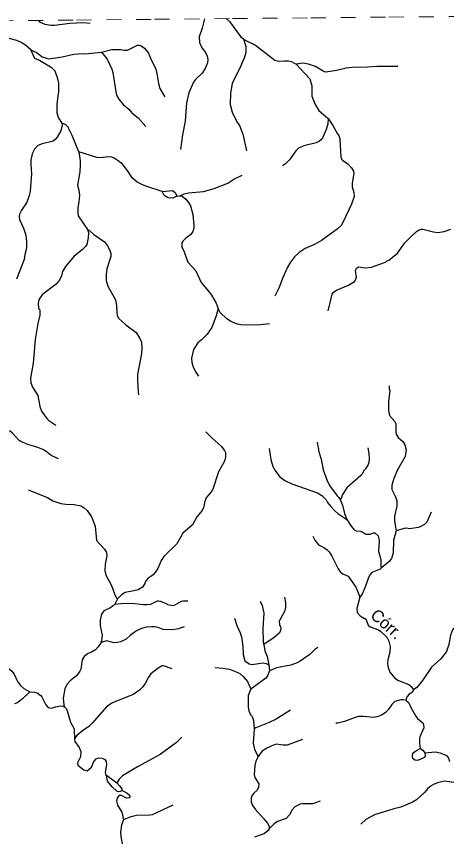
# Model space of a CAD drawing. Extents: x 346.5 to 372.4, y 7400.3 to 7428.2.
# Drawn here: x 359.2 to 362.07, y 7422.68 to 7428.16 of the extents above; entities that cross this region are included whole.
import ezdxf
from ezdxf.enums import TextEntityAlignment as Align

# ---------------------------------------------------------------- set-up
doc = ezdxf.new("R2010")
doc.units = 0
doc.header["$LTSCALE"] = 0.032
doc.linetypes.add('SHORT_DASHED', pattern=[2.7, 1.5, -1.2])
for name, color, linetype, lineweight in [('2', 7, 'Continuous', 25), ('53', 7, 'SHORT_DASHED', 13), ('7', 7, 'Continuous', 25)]:
    doc.layers.add(name, color=color, linetype=linetype, lineweight=lineweight)
doc.layers.add('61', color=7, linetype='Continuous')

msp = doc.modelspace()

# ---------------------------------------------------------------- linework, layer by layer
at = {"layer": '2'}
for points in [[(360.1729, 7426.9861), (360.242, 7426.9932), (360.2587, 7426.9788), (360.2709, 7426.9555), (360.2438, 7426.9425), (360.2123, 7426.9445), (360.1856, 7426.9603)], [(361.8965, 7423.2635), (361.9141, 7423.2527), (361.9279, 7423.2355), (361.9302, 7423.2133), (361.9226, 7423.2035), (361.8958, 7423.1911), (361.876, 7423.1845), (361.8606, 7423.1871), (361.8483, 7423.1979), (361.8447, 7423.2143), (361.8488, 7423.2333), (361.8606, 7423.2451)], [(359.7998, 7423.0853), (359.869, 7423.0347), (359.8883, 7423.0151), (359.9024, 7422.9939), (359.9058, 7422.9835), (359.8927, 7422.978), (359.8796, 7422.9754), (359.87, 7422.9793), (359.839, 7423.0083), (359.8067, 7423.0468)]]:
    msp.add_lwpolyline(points, close=True, dxfattribs=at)
at = {"layer": '53'}
msp.add_lwpolyline([(355.9458, 7428.0971), (356.4678, 7428.1021), (356.9898, 7428.1072), (357.5118, 7428.1122), (358.0338, 7428.1172), (358.5558, 7428.1222), (359.0778, 7428.1271), (359.5998, 7428.1321), (360.1218, 7428.137), (360.6438, 7428.1419), (361.1658, 7428.1468), (361.6878, 7428.1517), (362.2098, 7428.1565)], dxfattribs=at)
at = {"layer": '7'}
msp.add_line((360.2709, 7426.9555), (360.2939, 7426.9584), dxfattribs=at)
for points in [[(359.6922, 7428.1092), (359.6452, 7428.114), (359.5559, 7428.11), (359.4539, 7428.0949), (359.4284, 7428.0949), (359.3902, 7428.102), (359.36, 7428.1166), (359.3492, 7428.1297)], [(360.4549, 7428.1401), (360.4405, 7428.0773), (360.4206, 7428.02), (360.4214, 7427.9825), (360.4373, 7427.9466), (360.4612, 7427.9164), (360.474, 7427.8909), (360.4772, 7427.8685), (360.4756, 7427.8462), (360.4596, 7427.808), (360.4397, 7427.7769), (360.3959, 7427.7346), (360.3831, 7427.7179), (360.3513, 7427.6454), (360.3361, 7427.5785), (360.3258, 7427.4557), (360.3082, 7427.3649), (360.2955, 7427.2669)], [(360.5994, 7428.1415), (360.6222, 7428.122), (360.6967, 7428.0219), (360.7173, 7428.0074)], [(359.2939, 7427.9329), (359.2595, 7427.965), (359.2308, 7427.9825), (359.2021, 7427.9952), (359.1415, 7428.0104), (359.1235, 7428.0245)], [(360.7173, 7428.0074), (360.7314, 7427.9546), (360.7314, 7427.9164), (360.721, 7427.8781), (360.7083, 7427.8478), (360.6916, 7427.8096), (360.6509, 7427.7331), (360.6413, 7427.7076), (360.6286, 7427.6438), (360.627, 7427.5673), (360.6413, 7427.5163), (360.6724, 7427.4525), (360.69, 7427.4278), (360.7123, 7427.3697), (360.7354, 7427.2573)], [(360.7173, 7428.0074), (360.7283, 7427.9985), (360.796, 7427.965), (360.9267, 7427.863), (360.9522, 7427.8574), (360.9904, 7427.8606), (361.0159, 7427.859), (361.0374, 7427.8542), (361.068, 7427.8366)], [(359.5046, 7427.4438), (359.4794, 7427.4812), (359.4714, 7427.5099), (359.4714, 7427.5673), (359.4778, 7427.6247), (359.481, 7427.6534), (359.481, 7427.7108), (359.4746, 7427.7394), (359.4571, 7427.7912), (359.438, 7427.8103), (359.3519, 7427.8614), (359.3216, 7427.8749), (359.2939, 7427.9329)], [(359.2939, 7427.9329), (359.3376, 7427.9132), (359.371, 7427.8869), (359.4157, 7427.8733), (359.5049, 7427.8853), (359.5814, 7427.9036), (359.6452, 7427.9084), (359.6579, 7427.9068), (359.7663, 7427.9183)], [(359.7663, 7427.9183), (359.8364, 7427.9347), (359.8954, 7427.9347), (359.9177, 7427.9299), (359.94, 7427.9299), (360.0086, 7427.9642), (360.0197, 7427.9642), (360.0333, 7427.9594), (360.0556, 7427.9435), (360.0811, 7427.91), (360.0938, 7427.8765), (360.1313, 7427.804), (360.1377, 7427.7745), (360.1472, 7427.7076), (360.1576, 7427.6741), (360.1895, 7427.6191)], [(359.7663, 7427.9183), (359.8053, 7427.8701), (359.8372, 7427.8048), (359.8436, 7427.7809), (359.8619, 7427.6518), (359.8675, 7427.6311), (359.8826, 7427.604), (359.9121, 7427.5681), (359.9488, 7427.537), (359.9695, 7427.5131), (360.0126, 7427.4788), (360.0644, 7427.4199)], [(361.7467, 7427.8207), (361.6089, 7427.8223), (361.5451, 7427.8167), (361.4431, 7427.8151), (361.4016, 7427.8096), (361.3379, 7427.7944), (361.2654, 7427.7841), (361.2486, 7427.7896), (361.1968, 7427.8223), (361.1514, 7427.8382), (361.1132, 7427.8446), (361.068, 7427.8366)], [(361.068, 7427.8366), (361.1593, 7427.7402), (361.1729, 7427.6932), (361.1737, 7427.6231), (361.1944, 7427.5689), (361.2207, 7427.5274), (361.2821, 7427.4743)], [(359.5046, 7427.4438), (359.5052, 7427.4301), (359.4953, 7427.392), (359.4706, 7427.3489), (359.4579, 7427.333), (359.4443, 7427.3218), (359.371, 7427.3059), (359.3423, 7427.2931), (359.3192, 7427.27), (359.3049, 7427.239), (359.2953, 7427.1959), (359.2945, 7427.1672), (359.2993, 7427.1035), (359.2905, 7426.9887), (359.2849, 7426.9584), (359.2658, 7426.9106), (359.2315, 7426.8628), (359.2196, 7426.8341), (359.218, 7426.8198), (359.2196, 7426.799), (359.2459, 7426.7417), (359.2618, 7426.6939), (359.2666, 7426.6508), (359.2658, 7426.6078), (359.2539, 7426.5647), (359.2499, 7426.5329), (359.1989, 7426.4014)], [(359.6156, 7427.2515), (359.5718, 7427.3601), (359.5479, 7427.4047), (359.5463, 7427.4135), (359.5288, 7427.4326), (359.5046, 7427.4438)], [(361.2821, 7427.4743), (361.314, 7427.4286), (361.3442, 7427.372), (361.3538, 7427.3609), (361.3602, 7427.3394), (361.3674, 7427.2135), (361.3713, 7427.2095), (361.3721, 7427.2023), (361.3777, 7427.1967), (361.4136, 7427.1704), (361.4383, 7427.1449), (361.451, 7427.1234), (361.4526, 7427.1067), (361.4415, 7427.0429), (361.4415, 7427.0174), (361.4542, 7426.9792), (361.455, 7426.9537), (361.4383, 7426.9026), (361.3785, 7426.7751), (361.3682, 7426.76), (361.3411, 7426.7337), (361.2367, 7426.6596), (361.1897, 7426.6333), (361.1283, 7426.6054), (361.0876, 7426.5799), (361.0566, 7426.5496), (361.0295, 7426.5153), (361.0095, 7426.4819), (360.9761, 7426.4054), (360.953, 7426.3416), (360.9267, 7426.2866)], [(361.2821, 7427.4743), (361.2789, 7427.4382), (361.2693, 7427.3999), (361.2415, 7427.3386), (361.2247, 7427.3226), (361.2016, 7427.3107), (361.1195, 7427.2923), (361.0837, 7427.2756), (361.0669, 7427.2573), (361.0239, 7427.1975), (360.9976, 7427.1712), (360.9769, 7427.1585)], [(359.6156, 7427.2515), (359.6244, 7427.1911), (359.6252, 7427.1656), (359.6228, 7427.1178), (359.6077, 7427.0294), (359.6165, 7426.9951), (359.6197, 7426.9616), (359.6165, 7426.917), (359.6101, 7426.8803), (359.6093, 7426.8421), (359.6117, 7426.8229), (359.6734, 7426.7324)], [(360.1729, 7426.9861), (360.0644, 7427.0214), (360.0357, 7427.0325), (360.0062, 7427.0493), (359.9719, 7427.078), (359.9448, 7427.121), (359.9074, 7427.1688), (359.8795, 7427.1919), (359.8508, 7427.2103), (359.8364, 7427.215), (359.8078, 7427.2182), (359.7647, 7427.2118), (359.736, 7427.2126), (359.6156, 7427.2515)], [(360.2939, 7426.9584), (360.3194, 7426.9704), (360.3481, 7426.9783), (360.4485, 7426.9863), (360.5202, 7427.0062), (360.6119, 7427.0413), (360.6509, 7427.0684), (360.7075, 7427.0955)], [(360.2939, 7426.9584), (360.3053, 7426.9552), (360.3313, 7426.9361), (360.3497, 7426.913), (360.3616, 7426.8915), (360.3768, 7426.8325), (360.3847, 7426.7608), (360.3839, 7426.7417), (360.3776, 7426.7194), (360.364, 7426.7002), (360.3282, 7426.6731), (360.3106, 7426.6556), (360.305, 7426.6428), (360.3034, 7426.6157), (360.3186, 7426.5839), (360.3441, 7426.5153), (360.3983, 7426.4563), (360.4325, 7426.3783), (360.4827, 7426.3209), (360.5019, 7426.2946), (360.5346, 7426.2412), (360.5462, 7426.2041)], [(359.6734, 7426.7324), (359.6796, 7426.7117), (359.6778, 7426.6763), (359.6683, 7426.6333), (359.6603, 7426.6189), (359.6372, 7426.5966), (359.5854, 7426.5552), (359.5264, 7426.4858), (359.5065, 7426.4516), (359.5001, 7426.4229), (359.4874, 7426.3942), (359.465, 7426.3671), (359.383, 7426.3073), (359.3718, 7426.2962), (359.3511, 7426.2667), (359.3455, 7426.2523), (359.3439, 7426.238), (359.3471, 7426.2093), (359.3471, 7426.2037), (359.3543, 7426.195), (359.3559, 7426.1806), (359.3559, 7426.1591), (359.3423, 7426.1041), (359.324, 7425.9973), (359.3104, 7425.8395), (359.2937, 7425.7391), (359.2953, 7425.7088), (359.3057, 7425.6801), (359.3407, 7425.6228), (359.3543, 7425.5494), (359.3654, 7425.5176), (359.4013, 7425.4697), (359.4157, 7425.4554), (359.4611, 7425.4243)], [(359.6734, 7426.7324), (359.6877, 7426.7258), (359.7169, 7426.7002), (359.7862, 7426.65), (359.8077, 7426.6237), (359.8213, 7426.5982), (359.8285, 7426.5727), (359.8285, 7426.5512), (359.803, 7426.4691), (359.7982, 7426.4309), (359.7982, 7426.3926), (359.8101, 7426.3544), (359.8611, 7426.2619), (359.8683, 7426.2237), (359.8691, 7426.1726), (359.8723, 7426.1599), (359.8818, 7426.1408), (359.9297, 7426.0953), (359.9982, 7426.0443), (360.0229, 7426.0053), (360.0341, 7425.9798), (360.0373, 7425.9415), (360.0349, 7425.9033), (360.0086, 7425.763), (360.007, 7425.7248), (360.0118, 7425.6467), (360.0134, 7425.6267)], [(361.2821, 7426.1886), (361.3084, 7426.3009), (361.3156, 7426.3105), (361.3379, 7426.3264), (361.4176, 7426.3607), (361.4574, 7426.3862), (361.467, 7426.4006), (361.471, 7426.4149), (361.4638, 7426.4595), (361.4718, 7426.4731), (361.4837, 7426.4826), (361.5292, 7426.4755), (361.5722, 7426.4818), (361.6583, 7426.5129), (361.6869, 7426.5281), (361.7459, 7426.5751), (361.7953, 7426.6428), (361.8312, 7426.6819), (361.8718, 7426.7201), (361.8862, 7426.7289), (361.9053, 7426.7353), (361.9149, 7426.7353), (361.9866, 7426.7169), (362.0153, 7426.713), (362.0583, 7426.7201), (362.1014, 7426.7345)], [(360.5462, 7426.2041), (360.5346, 7426.1559), (360.5043, 7426.0786), (360.4724, 7426.0324), (360.4334, 7425.9941), (360.411, 7425.975), (360.3831, 7425.9304), (360.3688, 7425.873), (360.3704, 7425.8443), (360.3799, 7425.8156), (360.3935, 7425.7869), (360.415, 7425.7527)], [(360.8892, 7426.1025), (360.8294, 7426.0953), (360.7561, 7426.0929), (360.6987, 7426.0961), (360.6756, 7426.1009), (360.635, 7426.116), (360.6055, 7426.136), (360.5613, 7426.178), (360.5462, 7426.2041)], [(361.6901, 7425.6889), (361.6901, 7425.6674), (361.6933, 7425.6562), (361.6846, 7425.5813), (361.6853, 7425.5239), (361.6909, 7425.4905), (361.7268, 7425.4498), (361.7332, 7425.4315), (361.7332, 7425.3757), (361.7364, 7425.3645), (361.7507, 7425.343), (361.781, 7425.3151), (361.7937, 7425.2928), (361.8033, 7425.2593), (361.7969, 7425.2147), (361.7451, 7425.1271), (361.7212, 7425.0697), (361.7077, 7425.0234), (361.7085, 7424.9948), (361.7308, 7424.9501), (361.7411, 7424.9206), (361.7403, 7424.8832), (361.726, 7424.8162), (361.7252, 7424.7828), (361.7363, 7424.7183)], [(359.4802, 7425.1996), (359.4316, 7425.2235), (359.3965, 7425.2498), (359.3742, 7425.2625), (359.3407, 7425.2761), (359.2738, 7425.2952), (359.2276, 7425.3167), (359.2172, 7425.3231), (359.1734, 7425.3717), (359.1566, 7425.3861), (359.1256, 7425.3924), (359.0833, 7425.3924), (359.0395, 7425.4044), (358.9471, 7425.4562), (358.9083, 7425.4834)], [(360.4644, 7425.3813), (360.5059, 7425.339), (360.5672, 7425.2848), (360.5903, 7425.2562), (360.5951, 7425.2418), (360.5967, 7425.2131), (360.5887, 7425.1844), (360.5489, 7425.1127), (360.5106, 7424.9979), (360.5003, 7424.9804), (360.4676, 7424.9398), (360.4564, 7424.9087), (360.4501, 7424.88), (360.4389, 7424.8545), (360.4046, 7424.8123), (360.3744, 7424.7596), (360.3114, 7424.7031), (360.27, 7424.6321), (360.1847, 7424.5485), (360.1664, 7424.5198), (360.144, 7424.468), (360.1313, 7424.448), (360.1122, 7424.4257), (360.0755, 7424.3986), (360.0612, 7424.3811), (360.0564, 7424.3668), (360.0412, 7424.3429), (360.0118, 7424.3253), (359.9831, 7424.3181), (359.9257, 7424.3078), (359.9002, 7424.2918), (359.8734, 7424.2644), (359.8559, 7424.2289)], [(361.2088, 7425.3111), (361.2151, 7425.2721), (361.2183, 7425.2681), (361.2183, 7425.2554), (361.2375, 7425.19), (361.2375, 7425.1765), (361.2399, 7425.1757), (361.2494, 7425.1271), (361.2741, 7425.0601), (361.2909, 7425.0219), (361.3411, 7424.9533), (361.3539, 7424.9426), (361.3624, 7424.9273)], [(360.8884, 7425.2681), (360.8996, 7425.1956), (360.9123, 7425.1494), (360.9298, 7425.1175), (360.9585, 7425.08), (360.9928, 7425.0545), (361.0382, 7425.0322), (361.2104, 7424.974), (361.2407, 7424.9541), (361.2678, 7424.9254), (361.2773, 7424.9079), (361.298, 7424.8832), (361.3275, 7424.8521), (361.3474, 7424.8346), (361.4067, 7424.7953)], [(361.5475, 7425.2729), (361.5546, 7425.2354), (361.5554, 7425.2004), (361.5546, 7425.1757), (361.5491, 7425.1621), (361.5315, 7425.1342), (361.5196, 7425.1231), (361.5084, 7425.0984), (361.5004, 7425.0888), (361.4064, 7425.0067), (361.3785, 7424.9629), (361.3714, 7424.9411), (361.3624, 7424.9273)], [(359.2762, 7424.9924), (359.4053, 7424.9421), (359.4428, 7424.9198), (359.4954, 7424.9015), (359.5288, 7424.8967), (359.5846, 7424.8951), (359.6308, 7424.8856), (359.6516, 7424.8736), (359.6715, 7424.8553), (359.701, 7424.8131), (359.7249, 7424.7493), (359.7344, 7424.6545), (359.7862, 7424.5955), (359.7998, 7424.574), (359.8038, 7424.5517), (359.7926, 7424.4959), (359.7886, 7424.4512), (359.7982, 7424.4178), (359.8269, 7424.3675), (359.8404, 7424.3365), (359.8571, 7424.2919), (359.8685, 7424.271), (359.8734, 7424.2644)], [(361.3624, 7424.9273), (361.3777, 7424.8912), (361.3913, 7424.8354), (361.4067, 7424.7953)], [(361.9707, 7424.8441), (361.9412, 7424.778), (361.9252, 7424.7613), (361.8958, 7424.7453), (361.8846, 7424.7405), (361.8288, 7424.7326), (361.8033, 7424.7365), (361.7906, 7424.7349), (361.7363, 7424.7183)], [(361.4067, 7424.7953), (361.4351, 7424.7493), (361.455, 7424.7254), (361.4702, 7424.719), (361.4989, 7424.7158), (361.5132, 7424.711), (361.5347, 7424.6959), (361.5642, 7424.6959), (361.5849, 7424.7047), (361.5937, 7424.7047), (361.6152, 7424.6863), (361.6232, 7424.6553), (361.6176, 7424.5803), (361.628, 7424.5517), (361.6343, 7424.523), (361.633, 7424.4789), (361.6357, 7424.4699)], [(361.7363, 7424.7183), (361.7188, 7424.6569), (361.7156, 7424.5708), (361.7061, 7424.5349), (361.6901, 7424.5134), (361.6357, 7424.4699)], [(361.1801, 7424.6832), (361.192, 7424.6569), (361.2175, 7424.625), (361.2534, 7424.6074), (361.2757, 7424.5923), (361.2885, 7424.5788), (361.3068, 7424.5501), (361.3482, 7424.464), (361.365, 7424.4425), (361.3809, 7424.4313), (361.4152, 7424.4154), (361.4662, 7424.3429), (361.4813, 7424.311), (361.4934, 7424.275)], [(361.6357, 7424.4699), (361.6288, 7424.463), (361.573, 7424.4401), (361.561, 7424.4257), (361.5483, 7424.4002), (361.5315, 7424.3492), (361.5085, 7424.2963), (361.4934, 7424.275)], [(360.9896, 7424.2751), (360.9968, 7424.2393), (360.9968, 7424.209), (360.9904, 7424.1803), (360.9553, 7424.1157), (360.9561, 7424.0942), (360.9649, 7424.0711), (360.9633, 7424.0512), (360.9537, 7424.0344), (360.9219, 7424.0057), (360.851, 7423.9591)], [(361.4934, 7424.275), (361.4726, 7424.1994), (361.475, 7424.1723), (361.4949, 7424.1508), (361.5244, 7424.1333), (361.5291, 7424.1333), (361.5371, 7424.1253), (361.5483, 7424.0886), (361.5626, 7424.0767), (361.6184, 7424.0575), (361.6343, 7424.0472), (361.6734, 7424.0089), (361.6869, 7423.981), (361.6965, 7423.946), (361.6933, 7423.9077), (361.6798, 7423.8567), (361.679, 7423.8312), (361.6822, 7423.8057), (361.6941, 7423.7738), (361.7276, 7423.734), (361.7523, 7423.7196), (361.8208, 7423.6917), (361.8368, 7423.679), (361.8518, 7423.6558)], [(359.8559, 7424.2289), (359.8484, 7424.2199), (359.8237, 7424.2018), (359.7838, 7424.1835), (359.7663, 7424.1612), (359.7583, 7424.1229), (359.7583, 7424.0846), (359.7727, 7424.0225), (359.7683, 7423.9857), (359.7607, 7423.9671)], [(359.8559, 7424.2289), (359.8954, 7424.2337), (359.9703, 7424.236), (360.0468, 7424.2257), (360.0723, 7424.2257), (360.0962, 7424.2297), (360.1409, 7424.2504), (360.1488, 7424.2512), (360.1616, 7424.2496), (360.2046, 7424.2305), (360.2086, 7424.2257), (360.2445, 7424.2209), (360.2556, 7424.2225), (360.3019, 7424.248), (360.313, 7424.2512), (360.3441, 7424.252)], [(360.827, 7424.2484), (360.8406, 7424.2201), (360.8517, 7424.1691), (360.8462, 7424.0687), (360.8475, 7423.9757), (360.851, 7423.9591)], [(362.2552, 7424.244), (362.1866, 7424.1739), (362.1571, 7424.1117), (362.1125, 7424.0583), (362.0998, 7424.0225), (362.0894, 7423.9603), (362.0735, 7423.9125), (362.0344, 7423.8647), (361.9723, 7423.8073), (361.9125, 7423.7196), (361.875, 7423.6726), (361.8518, 7423.6558)], [(360.6557, 7424.1349), (360.6716, 7424.0862), (360.6939, 7424.0368), (360.7019, 7424.0113), (360.7123, 7423.9476), (360.7139, 7423.8934), (360.7258, 7423.8495), (360.7545, 7423.8312), (360.7721, 7423.8264), (360.8486, 7423.836), (360.8677, 7423.8336), (360.8848, 7423.8237)], [(360.3186, 7424.0783), (360.2795, 7424.0639), (360.2572, 7424.0591), (360.2238, 7424.0575), (360.1791, 7424.0599), (360.1457, 7424.0727), (360.1233, 7424.0775), (360.101, 7424.0783), (360.0676, 7424.0743), (360.0341, 7424.0655), (360.0022, 7424.0504), (359.96, 7424.0209), (359.9313, 7423.9962), (359.8946, 7423.9778), (359.8731, 7423.9723), (359.8508, 7423.9715), (359.8014, 7423.9842), (359.7725, 7423.9751), (359.7607, 7423.9671)], [(359.7607, 7423.9671), (359.7442, 7423.943), (359.7265, 7423.9244), (359.6994, 7423.9077), (359.677, 7423.8989), (359.6523, 7423.8798), (359.638, 7423.8567), (359.6284, 7423.7946), (359.6221, 7423.7802), (359.6021, 7423.7515), (359.5575, 7423.7156), (359.536, 7423.6925), (359.5224, 7423.6623), (359.5121, 7423.6017), (359.515, 7423.5546), (359.5211, 7423.5408)], [(360.851, 7423.9591), (360.8589, 7423.9173), (360.8733, 7423.8782), (360.8848, 7423.8237), (360.8892, 7423.7846)], [(361.2128, 7423.9404), (361.1928, 7423.9252), (361.1586, 7423.8918), (361.0956, 7423.8479), (361.0749, 7423.8376), (361.0319, 7423.8216), (360.9362, 7423.8025), (360.8892, 7423.7846)], [(359.1279, 7423.8156), (359.1686, 7423.7818), (359.1829, 7423.7611), (359.206, 7423.7117), (359.226, 7423.6862), (359.2491, 7423.6662), (359.2874, 7423.6422)], [(360.2389, 7423.7977), (360.1807, 7423.8169), (360.1727, 7423.8169), (360.1457, 7423.8017), (360.0962, 7423.7635), (360.0803, 7423.7404), (360.0588, 7423.6997), (360.0428, 7423.6766), (360.0213, 7423.6543), (359.9799, 7423.6264), (359.8412, 7423.5698), (359.8022, 7423.5451), (359.7057, 7423.4327), (359.6834, 7423.4112), (359.6412, 7423.3825), (359.6029, 7423.3506), (359.5929, 7423.3394), (359.5867, 7423.325)], [(360.5274, 7423.8057), (360.5776, 7423.8017), (360.6222, 7423.7937), (360.6669, 7423.7778), (360.6916, 7423.7651), (360.7147, 7423.7467), (360.7434, 7423.7125), (360.766, 7423.6612)], [(360.8892, 7423.7846), (360.8764, 7423.7491), (360.8645, 7423.7348), (360.766, 7423.6612)], [(360.766, 7423.6612), (360.7481, 7423.6176), (360.7481, 7423.5411), (360.7521, 7423.5156), (360.7641, 7423.4901), (360.7736, 7423.4774), (360.784, 7423.4519), (360.7882, 7423.3957)], [(361.8518, 7423.6558), (361.8455, 7423.6415), (361.8232, 7423.6272), (361.8097, 7423.612), (361.8033, 7423.5961), (361.8041, 7423.5845)], [(359.2874, 7423.6422), (359.2403, 7423.5961), (359.2013, 7423.5682), (359.1861, 7423.5634)], [(359.2874, 7423.6422), (359.3184, 7423.6407), (359.3439, 7423.6344), (359.3439, 7423.6296), (359.3615, 7423.6184), (359.3694, 7423.6089), (359.3957, 7423.5555), (359.4117, 7423.5379), (359.434, 7423.5331), (359.4587, 7423.5427), (359.4936, 7423.549), (359.5094, 7423.5477), (359.5211, 7423.5408)], [(359.5211, 7423.5408), (359.5314, 7423.5311), (359.5384, 7423.5172), (359.5591, 7423.4407), (359.5846, 7423.3969), (359.5867, 7423.325)], [(361.8041, 7423.5845), (361.7826, 7423.5905), (361.7666, 7423.5897), (361.7284, 7423.5778), (361.7069, 7423.5587), (361.6838, 7423.5236), (361.6638, 7423.5037), (361.6391, 7423.4877), (361.6168, 7423.4782), (361.5849, 7423.471), (361.518, 7423.479), (361.4845, 7423.4774), (361.4622, 7423.4718), (361.3921, 7423.4447), (361.3475, 7423.4343), (361.3339, 7423.4343)], [(361.8041, 7423.5845), (361.8215, 7423.5689), (361.8352, 7423.5379), (361.867, 7423.4806), (361.8782, 7423.4654), (361.9149, 7423.4359), (361.9196, 7423.424), (361.9212, 7423.4033), (361.8957, 7423.3435), (361.8925, 7423.3291), (361.8925, 7423.3005), (361.8965, 7423.2635)], [(361.0311, 7423.5204), (360.935, 7423.4598), (360.8884, 7423.4375), (360.7977, 7423.4026), (360.7882, 7423.3957)], [(360.7882, 7423.3957), (360.78, 7423.3005), (360.7896, 7423.2574), (360.8138, 7423.2114)], [(359.5867, 7423.325), (359.5888, 7423.3105), (359.6181, 7423.2718), (359.6292, 7423.2447), (359.626, 7423.2096), (359.6069, 7423.1689), (359.6093, 7423.1522), (359.65, 7423.1219), (359.6723, 7423.1163), (359.701, 7423.1395), (359.7145, 7423.1729), (359.732, 7423.196), (359.7472, 7423.2024), (359.7727, 7423.2008), (359.7902, 7423.192), (359.799, 7423.1777), (359.7998, 7423.1554), (359.791, 7423.1044), (359.7934, 7423.0917), (359.7998, 7423.0853)], [(360.305, 7423.3395), (360.2692, 7423.3036), (360.1584, 7423.2239), (360.007, 7423.1426), (359.9066, 7423.0813), (359.8843, 7423.0598), (359.869, 7423.0347)], [(361.1108, 7423.3252), (361.008, 7423.2869), (360.9793, 7423.2861), (360.9362, 7423.2925), (360.9219, 7423.2901), (360.8685, 7423.2646), (360.839, 7423.2439), (360.8138, 7423.2114)], [(361.9279, 7423.2355), (361.9994, 7423.2431), (362.0312, 7423.2351), (362.0719, 7423.2168), (362.0872, 7423.2001), (362.0934, 7423.1768)], [(360.8138, 7423.2114), (360.7991, 7423.1793), (360.7928, 7423.1506), (360.788, 7423.0901), (360.7912, 7423.0701), (360.8191, 7423.0287), (360.8167, 7423.0056), (360.8071, 7422.9857), (360.7848, 7422.9657), (360.772, 7422.9474), (360.7681, 7422.9323), (360.7673, 7422.9091), (360.7744, 7422.8892), (360.7936, 7422.8589), (360.8509, 7422.7968), (360.8756, 7422.7649), (360.8868, 7422.7458), (360.8868, 7422.7267)], [(362.1215, 7423.0371), (362.0599, 7423.047), (362.0137, 7423.0351), (361.985, 7423.0247), (361.9707, 7423.0151), (361.9452, 7422.9944), (361.9252, 7422.9713), (361.8718, 7422.9211), (361.8447, 7422.9052), (361.7666, 7422.8717), (361.7204, 7422.8613), (361.5913, 7422.8215), (361.5339, 7422.7912), (361.5013, 7422.7593)], [(359.9058, 7422.9835), (359.9369, 7422.9681), (359.9544, 7422.9522), (359.956, 7422.9418), (359.9512, 7422.9346), (359.9337, 7422.9322), (359.9018, 7422.9506), (359.8858, 7422.9514), (359.8715, 7422.9354), (359.8683, 7422.9115), (359.8731, 7422.886), (359.9034, 7422.8398), (359.9133, 7422.7874)], [(360.2437, 7422.8868), (360.1058, 7422.8215), (360.0899, 7422.8183), (360.0006, 7422.8159), (359.9576, 7422.8055), (359.9133, 7422.7874)], [(361.2287, 7422.9115), (361.1801, 7422.8948), (361.1084, 7422.8956), (361.094, 7422.8924), (361.059, 7422.8741), (361.0406, 7422.8542), (361.0231, 7422.8215), (361.0016, 7422.7976), (360.9434, 7422.7761), (360.9203, 7422.7601), (360.8868, 7422.7267)], [(359.9133, 7422.7874), (359.9018, 7422.7538), (359.8938, 7422.7059), (359.8954, 7422.6756), (359.9066, 7422.6151), (359.9058, 7422.5673), (359.9018, 7422.5386), (359.9034, 7422.5242), (359.9082, 7422.5186), (359.9289, 7422.5146), (359.9456, 7422.5298), (359.9711, 7422.5672), (359.9847, 7422.5704), (359.9934, 7422.5648), (360.0014, 7422.5585), (360.003, 7422.5465), (359.9998, 7422.5163), (360.0046, 7422.5043), (360.0197, 7422.486), (360.0269, 7422.4629), (360.003, 7422.4517), (359.9608, 7422.4246), (359.9568, 7422.4015), (359.9615, 7422.3629)], [(360.8868, 7422.7267), (360.882, 7422.7155), (360.8565, 7422.6971), (360.8407, 7422.6892), (360.7887, 7422.6729)]]:
    msp.add_lwpolyline(points, dxfattribs=at)

# ---------------------------------------------------------------- texts
at = {"layer": '61'}
msp.add_text('Córr.', height=0.08, rotation=318.487, dxfattribs=at).set_placement((361.6467, 7424.0664), align=Align.CENTER)

doc.saveas('drawing.dxf')
